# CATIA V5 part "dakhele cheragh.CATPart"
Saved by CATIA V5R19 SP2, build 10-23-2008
Part number: dakhele cheragh
Bounding box of the stored display mesh (mm): x 0 to 1135.087, y -799.286 to 803.447, z 0 to 678.786
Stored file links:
  C:\BEHROOZ\catia learning\tarh haye mashin\hb\dakhele cheragh.CATPart
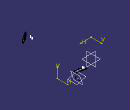
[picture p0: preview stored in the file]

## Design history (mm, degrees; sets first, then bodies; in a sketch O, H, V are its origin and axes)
Body1 (main body)
  DatumPoint1
  DatumPoint2
  Plane1: type OffsetPt, RefPlane xy-plane, RefPoint DatumPoint2
  Sketch1 on Plane1, origin (0, 0, 493.0265), H (1, 0, 0), V (0, 1, 0)
    line L1 (1106.376, 717.6367) -> (1106.376, 803.447)
  Plane2: type Angle, RefPlane Plane1, Direction Sketch1, Angle 18
  Sketch2 on Plane2, origin (129.6478, 0, 810.3847), H (0, 1, 0), V (-0.9511, 0, 0.309)
    arc A1 centre (214.0168, -600.9114) radius 614.8436 from (657.2079, -1027.0737) to (799.2862, -789.3057) ccw
    line L1 (799.2862, -789.3057) -> (696.9697, -916.543)
    arc A2 centre (609.8756, -917.7919) radius 87.103 from (696.9697, -916.543) to (661.6337, -987.8492) cw
    line L2 (661.6337, -987.8492) -> (657.2079, -1027.0737)
    arc A3 centre (-214.0168, -600.9114) radius 614.8436 from (-657.2079, -1027.0737) to (-799.2862, -789.3057) cw
    line L3 (-799.2862, -789.3057) -> (-696.9697, -916.543)
    arc A4 centre (-609.8756, -917.7919) radius 87.103 from (-696.9697, -916.543) to (-661.6337, -987.8492) ccw
    line L4 (-661.6337, -987.8492) -> (-657.2079, -1027.0737)
  Pad1: profile Sketch2, direction (0.309, 0, 0.9511), length 126, opposite side length -66
  Fillet1: radius 16, on edge [face of Pad1 from Sketch2.A1 | end face of Pad1]; edge [start face of Pad1 | face of Pad1 from Sketch2.A1]; edge [face of Pad1 from Sketch2.A3 | end face of Pad1]; edge [start face of Pad1 | face of Pad1 from Sketch2.A3]
  Plane3: stored without definition
  Fillet2: radius 10, on edge [face of Pad1 from Sketch2.A2 | end face of Pad1]; edge [face of Pad1 from Sketch2.A4 | end face of Pad1]; edge [start face of Pad1 | face of Pad1 from Sketch2.A4]; edge [start face of Pad1 | face of Pad1 from Sketch2.A2]
  Sketch3 on Plane3, origin (882, 0, 0), H (0, 1, 0), V (0, 0, 1)
    line L1 (696.9697, 611.7246) -> (696.9697, 585.095)
    unspec C1
    line L2 (657.2079, 570.9882) -> (657.2079, 597.6177)
    unspec C2
    line L3 (-696.9697, 611.7246) -> (-696.9697, 585.095)
    unspec C3
    line L4 (-657.2079, 570.9882) -> (-657.2079, 597.6177)
    unspec C4
  Plane4: type Angle, RefPlane Plane2, Direction Sketch1, Angle 90
  Sketch4 on Plane4, origin (855.8297, 0, -278.0759), H (0, 1, 0), V (0.309, 0, 0.9511)
    line L1 (698.6092, 920.7851) -> (698.6092, 892.7851)
    line L2 (698.6092, 892.7851) -> (657.2079, 892.7851)
    line L3 (657.2079, 892.7851) -> (657.2079, 920.7851)
    line L4 (657.2079, 920.7851) -> (698.6092, 920.7851)
    line L5 (-698.6092, 920.7851) -> (-698.6092, 892.7851)
    line L6 (-698.6092, 892.7851) -> (-657.2079, 892.7851)
    line L7 (-657.2079, 892.7851) -> (-657.2079, 920.7851)
    line L8 (-657.2079, 920.7851) -> (-698.6092, 920.7851)
  Pocket1: profile Sketch4, direction (-0.9511, 0, 0.309), length 126
  Fillet3: radius 14, on edge [face of Pad1 from Sketch2.A1 | face of Pocket1 from Sketch4.L1]; edge [face of Pocket1 from Sketch4.L5 | face of Pad1 from Sketch2.A3]
  Sketch5 on face of Pad1 from Sketch2.L3, origin (618.5434, -808.7834, -200.9769), H (-0.7943, -0.6075, 0), V (0.1176, -0.1538, 0.9811)
    line L1 (-394.1226, 859.767) -> (-382.8025, 814.6889)
    line L2 (-382.8025, 814.6889) -> (-254.3165, 848.6965)
    line L3 (-241.3846, 870.6163) -> (-242.8585, 876.4854)
    line L4 (-270.1425, 892.582) -> (-394.1226, 859.767)
    arc A1 centre (-264.4471, 871.064) radius 22.2589 from (-270.1425, 892.582) to (-242.8585, 876.4854) cw
    arc A2 centre (-258.9507, 866.2051) radius 18.1115 from (-254.3165, 848.6965) to (-241.3846, 870.6163) ccw
  Pocket2: profile Sketch5, direction (0.596, -0.7793, -0.1936), length 1
  DatumSurface1
  Mirror1: of Pocket2, about zx-plane
  DatumSurface2
  Split1: SplitPlane DatumSurface1
  Split2: SplitPlane DatumSurface2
